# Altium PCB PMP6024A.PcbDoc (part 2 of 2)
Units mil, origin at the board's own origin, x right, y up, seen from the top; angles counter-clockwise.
Board outline 5700 x 1771.65 mil, 2 copper layers (Top Layer, Bottom Layer), stack 62 mil thick; 185 components, 92 nets, 398 pads, 91 vias.
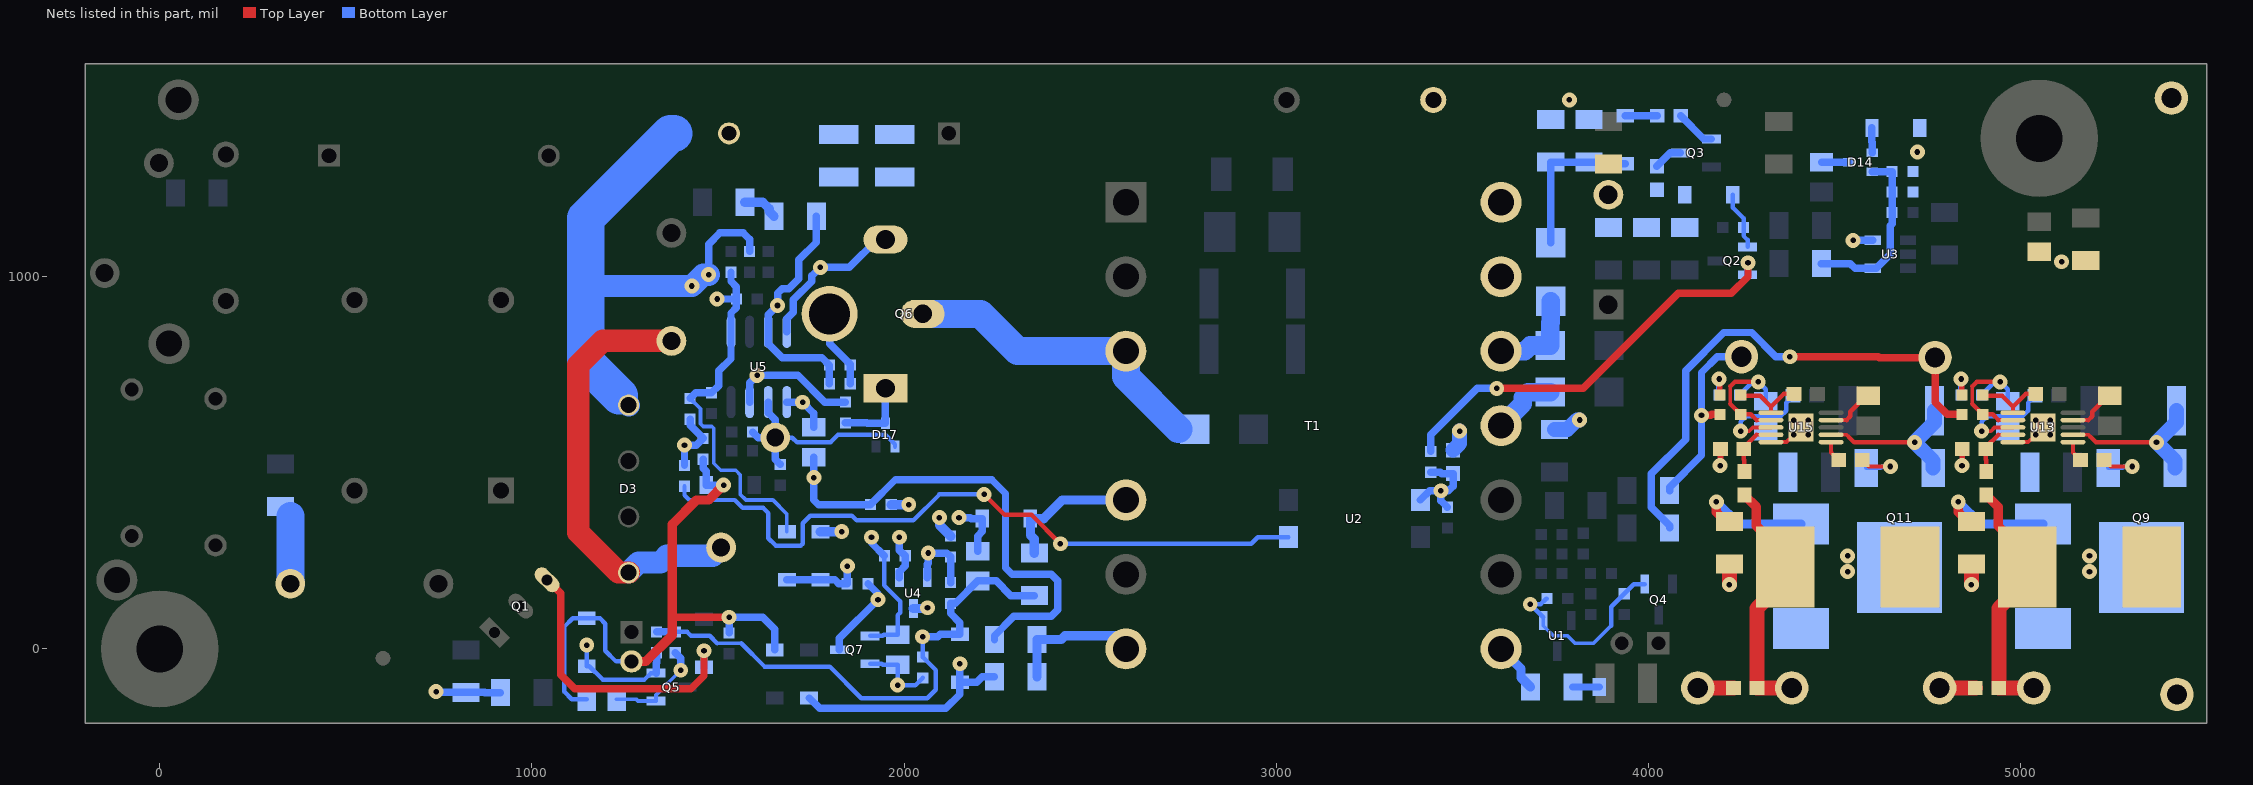
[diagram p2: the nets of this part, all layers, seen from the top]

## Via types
v1: diameter 40, hole 15, Top Layer to Bottom Layer, 82 vias
v2: diameter 25, hole 15, Top Layer to Bottom Layer, 8 vias
v3: diameter 40, hole 15, Top Layer to Bottom Layer, tented bottom, 1 vias

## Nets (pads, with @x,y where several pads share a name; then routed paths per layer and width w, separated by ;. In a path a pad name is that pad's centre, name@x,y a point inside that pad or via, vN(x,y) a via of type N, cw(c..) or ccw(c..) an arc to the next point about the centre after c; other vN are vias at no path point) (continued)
NetC24_1: C24.1 D11.1 R13.2 R17.2 R27.1 R35.2 R40.2 | length 1447.8
  Bottom Layer w10: 1497.5,15 1562.5,15
  Bottom Layer w12: R13.2@1385,45.5 1417,45.5 1427.5,35 1477.5,35 1497.5,15 ; 1562.5,15 1625,-47.5 1800,-47.5 1885,-132.5 2062.5,-132.5 2085,-110 2085,-57 R27.1@2050,-22 v1(2050,32.5)
  Bottom Layer w20: R17.2@1335,45.5 R13.2@1380.5,45.5 ; v1(2050,32.5) 2090,32.5 2096.97,39.47 D11.1@2150,39.47 2150,70 2125,95 R35.2@2125,122 2137,122 R40.2@2197.5,182.5 2247.5,182.5 2287.09,142.91 C24.1@2350,142.91
NetC25_2: C25.2 R19.1 R44.1 | length 1319.5
  Bottom Layer w20: R44.1@1757.5,515 v1(1757.5,460) 1757.5,400 1770,387.5 C25.2@1909.5,387.5 1977,455 2235,455 2272.5,417.5 2272.5,217.5 2290,200 2395,200 2412.5,182.5 2412.5,105 2395,87.5 2295,87.5 2242.91,35.41 R19.1@2242.91,25
NetC26_1: C26.1 R24.1 R45.2 U5.3 | length 644.7
  Bottom Layer w20: R24.1@1764.59,1162.5 1764.59,1092.09 1717.5,1045 1717.5,995 1690,967.5 1672.5,967.5 1660,955 v1(1660,922.5) 1635,897.5 U5.3@1635,851.99 1635,820 1672.5,782.5 1779.5,782.5 R45.2@1799.5,762.5 C26.1@1799.5,712.5
NetC27_1: C27.1 D20.2 D21.1 R7.2 | length 418.7
  Bottom Layer w20: D21.1@3737.5,1091.24 C27.1@3737.5,1307.91 R7.2@3840,1307.91 3892.09,1307.91 3896.97,1303.03 D20.2@3937.5,1303.03
NetC35_1: C35.1 D14.2 R21.2 R29.1 R41.2 U3.4 | length 483.7
  Bottom Layer w20: R21.2@4464.59,1035 4542.5,1035 4554.9,1022.6 U3.4@4602.76,1022.6 4612.6,1022.6 4650,1060 4650,1137.5 4654.5,1142 R29.1@4654.5,1172.5 C35.1@4654.5,1227.5 4654.5,1254.5 R41.2@4654.5,1282.5 4628.68,1282.5 4628.09,1281.91 D14.2@4601.5,1281.91
NetC66_1: C66.1 U13.9 | length 133.7
  Top Layer w10: U13.9@5140.71,614.69 5182.19,614.69
  Top Layer w12: 5182.19,614.69 5192.5,625 5192.5,637.5 5235,680 C66.1@5240,680
NetC68_1: C68.1 R46.1 R77.1 U13.2 | length 379.2
  Top Layer w10: 4870,658 4870,705 ; 4940.31,614.69 U13.2@4979.29,614.69
  Top Layer w12: 4870,658 R77.1@4898,630 4925,630 4940.31,614.69 ; 4870,705 4882.5,717.5 v1(4945,717.5)
  Bottom Layer w12: R46.1@4895.5,682.5 4930.5,717.5 v1(4945,717.5) 4965,697.5 C68.1@4965,665
NetC70_1: C70.1 R82.2 U13.4 | length 152.2
  Top Layer w10: 4940.31,575.32 U13.4@4979.29,575.32
  Top Layer w12: R82.2@4907.5,476.5 4907.5,507.5 4906.5,508.5 C70.1@4906.5,537.5 4906.5,541.5 4940.31,575.32
NetC76_1: C76.1 U15.9 | length 133.7
  Top Layer w10: U15.9@4490.71,614.69 4532.19,614.69
  Top Layer w12: 4532.19,614.69 4542.5,625 4542.5,637.5 4585,680 C76.1@4590,680
NetC78_1: C78.1 R48.1 R87.1 U15.2 | length 379.2
  Top Layer w10: 4220,658 4220,705 ; 4290.31,614.69 U15.2@4329.29,614.69
  Top Layer w12: 4220,658 R87.1@4248,630 4275,630 4290.31,614.69 ; 4220,705 4232.5,717.5 v1(4295,717.5)
  Bottom Layer w12: R48.1@4245.5,682.5 4280.5,717.5 v1(4295,717.5) 4315,697.5 C78.1@4315,665
NetC80_1: C80.1 R92.2 U15.4 | length 152.2
  Top Layer w10: 4290.31,575.32 U15.4@4329.29,575.32
  Top Layer w12: R92.2@4257.5,476.5 4257.5,507.5 4256.5,508.5 C80.1@4256.5,537.5 4256.5,541.5 4290.31,575.32
NetC81_1: C81.1 Q5.1 R13.1 | length 271.3
  Bottom Layer w10: C81.1@1227.5,-135 1280,-135 1284.9,-139.9 Q5.1@1333.66,-139.9 1333.66,-123.84 v1(1400,-57.5)
  Bottom Layer w20: R13.1@1385,-10.5 1400,-25.5 v1(1400,-57.5)
NetD1_2: D1.2 D21.2 T1.12 | length 257.8
  Bottom Layer w50: T1.12@3603.94,800 3667.5,800 3682.5,815 D1.2@3736.26,815 3736.26,876.26 3737.5,877.5 D21.2@3737.5,933.76
NetD3_1: D3.1 L1.1 RV1.2 | length 1182.5
  Top Layer w60: D3.1@1260,205 1232.5,205 1125,312.5 1125,762.5 1190,827.5 L1.1@1375,827.5
  Bottom Layer w60: D3.1@1260,205 1287,232 1344.5,232 1362.5,250 1485.8,250 RV1.2@1508.17,272.36
NetD4_2: D4.2 Q6.2 T1.3 | length 856.1
  Bottom Layer w75: Q6.2@2050,900 2205,900 2305,800 T1.3@2596.06,800 2596.06,731.44 2737.5,590
NetD5_2: D5.2 T1.11 | length 179.2
  Bottom Layer w50: T1.11@3603.94,600 3662.5,658.56 3662.5,675 3677.5,690 D5.2@3736.26,690
NetD6_1: D6.1 Q2.1 R5.1 | length 156.4
  Bottom Layer w12: D6.1@4226.97,1220 4226.97,1185.53 4255.5,1157 R5.1@4255.5,1132.5 4255.5,1109.5 4266.34,1098.66 Q2.1@4266.34,1079.9
NetD7_2: D7.2 R8.2 | length 70.9
  Bottom Layer w20: R8.2@3797.09,-102.5 D7.2@3868.03,-102.5
NetD9_2: D9.2 Q1.3 | length 797.9
  Top Layer w20: Q1.3@1040.71,185.71 1077.5,148.92 1077.5,-70 1115,-107.5 1427.5,-107.5 1462.5,-72.5 v3(1462.5,-5)
  Bottom Layer w20: D9.2@1462.5,-49.47 v3(1462.5,-5)
NetD10_2: D10.2 D11.2 R12.2 | length 613.6
  Bottom Layer w20: D10.2@1745,-131.97 1773.03,-160 2112.5,-160 2150,-122.5 D11.2@2150,-89.47 ; v1(2150,-40) D11.2@2150,-89.47 ; R12.2@2242.91,-75 2210,-75 2195.53,-89.47 D11.2@2150,-89.47
NetD12_1: D12.1 Q5.2 R17.1 | length 320.2
  Bottom Layer w12: v1(1147.5,10) D12.1@1147.5,-46.97 1154.47,-46.97 1190,-82.5 1302.5,-82.5 1319.9,-65.1 Q5.2@1333.66,-65.1
  Bottom Layer w20: Q5.2@1333.66,-65.1 1333.66,-38.84 1335,-37.5 R17.1@1335,-10.5
NetD14_1: D14.1 D15.2 | length 67.3
  Bottom Layer w20: D15.2@4600.53,1400 4600.53,1361.97 4601.5,1361 D14.1@4601.5,1333.09
NetD14_3: D14.3 R22.1 | length 73.5
  Bottom Layer w20: R22.1@4465,1307.5 D14.3@4538.5,1307.5
NetD16_1: D16.1 D19.2 R36.2 | length 214.1
  Bottom Layer w20: D19.2@1685,185.53 D16.1@1775,185.53 1814.47,185.53 1825,175 R36.2@1847,175 1847,222 v1(1847.5,222.5)
NetD17_3: D17.3 Q6.1 R30.2 | length 201.2
  Bottom Layer w20: R30.2@1842.5,607 1900,607 1900.5,606.5 D17.3@1950,606.5 Q6.1@1950,700
NetD18_1: D18.1 R40.1 | length 157
  Bottom Layer w20: v1(2147.5,352.5) 2177.5,352.5 2180,350 D18.1@2210.53,350 2210.53,315.53 2197.5,302.5 R40.1@2197.5,262.5
NetD19_1: D19.1 R25.2 R31.2 R32.2 R34.2 U5.1 | length 1019.1
  Bottom Layer w10: R31.2@1425,673 1453,645 1453,605.03 1460.53,597.5 1483.5,597.5 1488.5,592.5 1488.5,499 1507.5,480 1547.5,480 1560,467.5 1560,415 1575,400 1647.5,400 1685,362.5 D19.1@1685,314.47
  Bottom Layer w20: R31.2@1425,673 1440,688 R25.2@1482.5,688 1502,707.5 1502,747 1535,780 U5.1@1535,851.99 1535,902.5 1549.5,917 R34.2@1549.5,940 ; v1(1497.5,940) R34.2@1549.5,940 ; R32.2@1535,1012 1535,987.5 1549.5,973 R34.2@1549.5,940
NetD20_1: D20.1 R6.1 | length 86.2
  Bottom Layer w20: D20.1@3937.5,1431.97 3981.97,1431.97 3982.5,1432.5 R6.1@4023.5,1432.5
NetD30_1: D30.1 L6.1 Q9.4
  other v1: 5185,207.5 5185,250
NetD30_2: D30.2 L8.2 | length 325.2
  Top Layer w25: v1(4832.5,395) 4832.5,367.5 4857.91,342.09 L8.2@4867.5,342.09
  Bottom Layer w25: v1(4832.5,395) 4892.01,335.49 D30.2@5060,335.49
NetD32_1: D32.1 L7.1 Q11.4
  other v1: 4535,207.5 4535,250
NetD32_2: D32.2 L9.2 | length 325.2
  Top Layer w25: v1(4182.5,395) 4182.5,367.5 4207.91,342.09 L9.2@4217.5,342.09
  Bottom Layer w25: v1(4182.5,395) 4242.01,335.49 D32.2@4410,335.49
NetF1_2: F1.2 L3.2 | length 181.9
  Bottom Layer w75: F1.2@350.98,175 350.98,356.93
NetQ2_2: Q2.2 R18.2 | length 1143.4
  Top Layer w20: v1(3592.5,700) 3825,700 4080,955 4222.5,955 4267.5,1000 v1(4267.5,1037.5)
  Bottom Layer w20: R18.2@3415,530.5 3415,575 3540,700 v1(3592.5,700) ; Q2.2@4266.34,1005.1 4266.34,1036.34 v1(4267.5,1037.5)
NetQ3_1: Q3.1 R6.2 | length 108.3
  Bottom Layer w20: R6.2@4086.5,1432.5 4149.09,1369.9 Q3.1@4168.84,1369.9
NetQ3_3: Q3.3 R9.2 | length 78.6
  Bottom Layer w20: R9.2@4022.5,1296.5 4058.5,1332.5 Q3.3@4086.16,1332.5
NetQ4_1: Q4.1 R10.1 R14.2 U1.1 | length 510.4
  Bottom Layer w10: U1.1@3717.6,84.9 U1.1@3717.6,76.34 3717.6,62.4 3745,35 3782.5,35 3802.5,15 3852.5,15 3900,62.5
  Bottom Layer w12: U1.1@3717.6,84.9 v1(3682.5,120) 3710,120 3725,135 R14.2@3727,135 ; 3900,62.5 3900,113 R10.1@3935,148 3960.84,173.84 Q4.1@3990.1,173.84
NetQ6_3: Q6.3 R38.2 R39.2 U5.4 | length 416.4
  Bottom Layer w20: U5.4@1685,851.99 1685,887.5 1702.5,905 1702.5,937.5 1752.5,987.5 1752.5,1002.5 v1(1775,1025) 1852.5,1025 1927.5,1100 Q6.3@1950,1100
NetQ7_1: Q7.1 R28.1 R33.2 | length 372.4
  Bottom Layer w12: Q7.1@1908.84,34.9 1942.4,34.9 1945,37.5 R28.1@1982.5,37.5 1982.5,90 1990,97.5 1990,127.5 1947,170.5 R33.2@1947,250
  Bottom Layer w20: v1(1912.5,300) 1912.5,284.5 R33.2@1947,250
NetQ7_2: Q7.2 R27.2 R28.2 | length 205.3
  Bottom Layer w12: Q7.2@1908.84,-39.9 1939.9,-39.9 1942.5,-42.5 R28.2@1982.5,-42.5 v1(1982.5,-97.5) 2030.5,-97.5 R27.2@2050,-78
NetQ7_3: Q7.3 R36.1 | length 231.7
  Bottom Layer w20: Q7.3@1826.16,-2.5 1826.16,28.66 v1(1930,132.5) 1930,148 R36.1@1903,175
NetQ9_1: Q9.1 R150.2 | length 149.5
  Top Layer w12: R150.2@5224,507.5 5241.5,490 v1(5300,490)
  Bottom Layer w12: Q9.1@5235.24,486.36 5273.86,486.36 5277.5,490 v1(5300,490)
NetQ9_3: Q9.3 R79.1 U13.7 | length 429.2
  Top Layer w10: U13.7@5140.71,575.32 5182.19,575.32 5187.5,570
  Top Layer w12: 5187.5,570 5202.5,555 v1(5365,555)
  Bottom Layer w40: Q9.3@5414.76,486.36 5414.76,505.24 v1(5365,555) 5418.64,608.64 R79.1@5418.64,640
NetQ11_1: Q11.1 R151.2 | length 149.5
  Top Layer w12: R151.2@4574,507.5 4591.5,490 v1(4650,490)
  Bottom Layer w12: Q11.1@4585.24,486.36 4623.86,486.36 4627.5,490 v1(4650,490)
NetQ11_3: Q11.3 R89.1 U15.7 | length 429.2
  Top Layer w10: U15.7@4490.71,575.32 4532.19,575.32 4537.5,570
  Top Layer w12: 4537.5,570 4552.5,555 v1(4715,555)
  Bottom Layer w40: Q11.3@4764.76,486.36 4764.76,505.24 v1(4715,555) 4768.64,608.64 R89.1@4768.64,640
NetR1_2: R1.2 R4.1 | length 173.9
  Bottom Layer w20: v1(742.5,-115) 744.59,-117.09 R4.1@822.5,-117.09 872.91,-117.09 873.33,-117.5 R1.2@915.41,-117.5
NetR8_1: R8.1 T1.8 | length 135.2
  Bottom Layer w25: T1.8@3603.94,0 3657.5,-53.56 3657.5,-77.09 R8.1@3682.91,-102.5
NetR12_1: R12.1 R19.2 T1.7 | length 322.1
  Bottom Layer w25: R12.1@2357.09,-75 R19.2@2357.09,25 2422.5,25 2432.5,35 T1.7@2575,35
NetR18_1: R18.1 R23.2 R50.2 U2.1 | length 250.1
  Bottom Layer w20: U2.1@3387.17,400 3412.17,425 v1(3442.5,425) ; R18.1@3415,474.5 3440.5,474.5 3444,471 R50.2@3475,471 3475,437.5 3462.5,425 v1(3442.5,425) ; R23.2@3460,380.5 3442.5,398 v1(3442.5,425)
NetR20_1: R20.1 R24.2 | length 98
  Bottom Layer w25: R20.1@1572.09,1200 1620,1200 1637.5,1182.5 1637.5,1175.41 R24.2@1650.41,1162.5
NetR30_1: R30.1 U5.7 | length 347.6
  Bottom Layer w20: U5.7@1585,663.01 1585,715 v1(1605,735) 1715,735 1787,663 R30.1@1842.5,663
NetR31_1: R31.1 R37.2 R43.1 | length 178
  Bottom Layer w20: R43.1@1410,493 v1(1410,547.5) 1442,547.5 R37.2@1460,565.5 1425,600.5 R31.1@1425,617
NetR33_1: R33.1 U4.1 | length 121.5
  Bottom Layer w20: v1(1987.5,300) 1987.5,265.5 R33.1@2003,250 2003,223 1987.6,207.6 U4.1@1987.6,191.34
NetR35_1: R35.1 R42.2 U4.2 | length 200.6
  Bottom Layer w20: U4.2@2062.4,191.34 2062.4,227.4 2065,230 v1(2065,257.5) 2114.5,257.5 R42.2@2125,247 R35.1@2125,178
NetR43_2: R43.2 U2.3 | length 1904.5
  Top Layer w12: v1(2215,415) 2270,360 2342.5,360 v1(2420,282.5)
  Bottom Layer w12: R43.2@1410,437 1410,412.5 1422.5,400 1545,400 1566.25,378.75 1621.25,378.75 1635,365 1635,297.5 1655,277.5 1722.5,277.5 1727.5,282.5 1727.5,337.5 1747.5,357.5 1860,357.5 1872.5,345 2025,345 2095,415 v1(2215,415) ; v1(2420,282.5) 2932.5,282.5 2950,300 U2.3@3032.83,300
NetR44_2: R44.2 U5.5 | length 122.6
  Bottom Layer w20: U5.5@1685,663.01 1726.99,663.01 v1(1727.5,662.5) 1757.5,632.5 R44.2@1757.5,595
NetR47_2: R47.2 U13.3 | length 298.5
  Top Layer w10: v1(4895,585) 4920,585 4930,595 U13.3@4979.29,595
  Bottom Layer w12: v1(4895,585) 4895,610 4910,625 5005,625 5020,640 5020,661.5 R47.2@5038.5,680
NetR49_2: R49.2 U15.3 | length 293.5
  Top Layer w10: v1(4247.5,585) 4270,585 4280,595 U15.3@4329.29,595
  Bottom Layer w12: v1(4247.5,585) 4247.5,610 4262.5,625 4355,625 4370,640 4370,661.5 R49.2@4388.5,680
NetR75_2: R75.2 R81.2 U13.1 | length 177.2
  Top Layer w10: U13.1@4979.29,634.37 4979.29,650.71
  Top Layer w12: R81.2@4906.5,680 4950,680 4979.29,650.71 5013.58,685 R75.2@5041,685
NetR85_2: R85.2 R91.2 U15.1 | length 177.2
  Top Layer w10: U15.1@4329.29,634.37 4329.29,650.71
  Top Layer w12: R91.2@4256.5,680 4300,680 4329.29,650.71 4363.58,685 R85.2@4391,685
NetR150_1: R150.1 U13.6 | length 56.5
  Top Layer w10: 5140.71,527.8 U13.6@5140.71,555.63
  Top Layer w12: 5140.71,527.8 R150.1@5161,507.5
NetR151_1: R151.1 U15.6 | length 56.5
  Top Layer w10: 4490.71,527.8 U15.6@4490.71,555.63
  Top Layer w12: 4490.71,527.8 R151.1@4511,507.5
PGND: C2.2 C10.2 C17.2 C20.2 C22.2 C24.2 C25.1 C26.2 C36.2 C81.2 D3.4 D8.2 D12.2 D13.2 D16.2 D17.1 D18.2 HTSK1.1 R37.1 R38.1 R39.1 R42.1 R45.1 RV1.1 T1.5 U4.3 U5.6 | length 4503.9
  Top Layer w20: 1377.5,85 v1(1530,85)
  Top Layer w25: C17.2@1267.5,-33.74 1306.26,-33.74 1377.5,37.5 1377.5,85 1377.5,335 1442.5,400 1475,400 v1(1515,440)
  Bottom Layer w12: C81.2@1147.5,-135 1107.5,-135 1087.5,-115 1087.5,60 1109.47,81.97 D12.2@1147.5,81.97 1183.03,81.97 1197.5,67.5 1197.5,-5 1226.24,-33.74 C17.2@1267.5,-33.74 ; RV1.1@1653.83,567.64 1699.86,567.64 1712.5,555 1802.5,555 1822.5,575 1950,575 1975.59,549.41 D17.1@1975.59,543.5
  Bottom Layer w20: R37.1@1460,509.5 1460,485 1468.03,476.97 D13.2@1468.03,440 v1(1515,440) ; v1(1475,1005.5) 1475,1087.5 1505,1117.5 1567.5,1117.5 1585,1100 C36.2@1585,1068 ; C10.2@1530,43 v1(1530,85) 1620,85 1652.5,52.5 D8.2@1652.5,-3.03 ; C20.2@1593,582.5 1607.86,567.64 RV1.1@1653.83,567.64 ; U5.6@1635,663.01 1635,635 1653.83,616.17 RV1.1@1653.83,567.64 ; C22.2@1667.5,495.5 1653.83,509.17 RV1.1@1653.83,567.64 ; HTSK1.1@1800,900 1800,820 1855.5,764.5 R45.1@1855.5,762.5 C26.2@1855.5,712.5
  Bottom Layer w25: D16.2@1775,314.47 1831.97,314.47 v1(1832.5,315) ; C25.1@1965.5,387.5 v1(2012.5,387.5) ; U4.3@2025,108.66 2061.16,108.66 v1@2062.5,110 ; v1(2095,352.5) 2095,333 R42.1@2125,303 ; C24.2@2350,257.09 2350,295 2339.47,305.53 D18.2@2339.47,350 2375,350 2425,400 T1.5@2596.06,400
  Bottom Layer w60: 1145,975 v1(1430,975) 1460.5,1005.5 v1(1475,1005.5) ; 1235,680 D3.4@1260,655
  Bottom Layer w100: 1235,680 1145,770 1145,975 1145,1157.5 1372.5,1385 1382.09,1385
  other v1: 2063.03,110.53
PWM1_IADJ: J4.1 R52.2 R77.2 | length 1427.2
  Top Layer w20: v1(4380,785) 4617.5,785 4620,782.5 J4.1@4770,782.5 4770,662.5 4802.5,630 R77.2@4842,630
  Bottom Layer w20: R52.2@4057.09,325 4057.09,330.41 4007.5,380 4007.5,470 4100,562.5 4100,747.5 4202.5,850 4277.5,850 4342.5,785 v1(4380,785)
PWM2_IADJ: J5.1 R53.2 R87.2 | length 528.5
  Top Layer w20: v1(4142.5,627.5) 4167.5,627.5 4170,630 R87.2@4192,630
  Bottom Layer w20: R53.2@4057.09,425 4057.09,434.59 4142.5,520 v1(4142.5,627.5) 4142.5,742.5 4185,785 J5.1@4250,785
SGND: C1.1 C5.2 C6.2 C7.2 C9.2 C27.2 C35.2 C40.1 C42.2 C64.1 C68.2 C70.2 C72.2 C74.1 C78.2 C80.2 C82.2 D6.2 D15.1 J6.1 J7.1 J8.1 J11.1 L8.1 L9.1 R7.1 R9.1 R41.1 R46.2 R48.2 R50.1 R51.2 R76.2 R81.1 R91.1 T1.13 T1.14 U3.5 U13.5 U13.11 U15.5 U15.11 | length 893.2
  Top Layer w10: U15.5@4329.29,555.63 4370.63,555.63 v2(4390.31,575.31) ; U13.5@4979.29,555.63 5020.63,555.63 v2(5040.31,575.31)
  Top Layer w15: v1(4190,725) 4192,723 R91.1@4192,682.5 ; v1(4192.5,492.5) 4193.5,493.5 C80.2@4193.5,537.5 ; v1(4840,725) 4842,723 R81.1@4842,682.5 ; v1(4842.5,492.5) 4843.5,493.5 C70.2@4843.5,537.5
  Top Layer w40: J11.1@4132.5,-105 C82.2@4228.5,-105 ; v1(4217.5,172.5) L9.1@4217.5,227.91 ; J6.1@4782.5,-105 C72.2@4878.5,-105 ; v1(4867.5,172.5) L8.1@4867.5,227.91
  Bottom Layer w15: R48.2@4189.5,682.5 4189.5,724.5 v1(4190,725) ; R46.2@4839.5,682.5 4839.5,724.5 v1(4840,725)
  Bottom Layer w20: v1(4550,1097.5) 4550.1,1097.4 U3.5@4602.76,1097.4
  Bottom Layer w40: R50.1@3475,534 3492.5,551.5 v1(3492.5,585) ; R51.2@3747.5,589.59 3782.09,589.59 3807.5,615 v1(3815,615)
  other v1: 5110,1040 4722.5,1335 3787.5,1475
  other v2: 4429.69,575.31 5079.69,575.31 4390.31,614.68 4429.69,614.68 5040.31,614.68 5079.69,614.68
VLED1: C72.1 J9.1 L6.2 R82.1 | length 689.4
  Top Layer w25: R82.1@4907.5,413.5 4940,381 4940,330 5017.98,252.02 L6.2@5017.98,220
  Top Layer w40: L6.2@5017.98,220 5017.98,185.48 4941.5,109 C72.1@4941.5,-105 J9.1@5035,-105
VLED2: C82.1 J13.1 L7.2 R92.1 | length 689.4
  Top Layer w25: R92.1@4257.5,413.5 4290,381 4290,330 4367.98,252.02 L7.2@4367.98,220
  Top Layer w40: L7.2@4367.98,220 4367.98,185.48 4291.5,109 C82.1@4291.5,-105 J13.1@4385,-105
pads on no net: FID1.1 FID2.1 FID3.1 FID4.1 T1.2 T1.4 T1.6 T1.10 U3.1 U3.2

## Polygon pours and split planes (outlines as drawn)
EGND on Bottom Layer "Bottom Layer-EGND" (solid, remove dead copper, pour order 15): 157.5,307.5 17.5,307.5 -57.5,382.5 -105,382.5 -157.5,330 -157.5,-30 -32.5,-155 57.5,-155 155,-57.5 155,195 177.5,217.5 177.5,287.5
NetQ6_3 on Bottom Layer "Bottom Layer-NetQ6_3" (solid, remove dead copper, pour order 20): 1772.5,1300 2035,1300 2035,1087.5 2007.5,1060 2005,1062.5 1902.5,1062.5 1875,1090 1875,1217.5 1850,1242.5 1772.5,1242.5
NetD30_1 on Bottom Layer "Bottom Layer-NetD30_1" (solid, remove dead copper, pour order 23): 4985,0 5345,0 5440,95 5440,340 5212.5,340 5167.5,295 5167.5,140 5137.5,110 4985,110
SGND on Bottom Layer "Bottom Layer-SGND" (solid, remove dead copper, pour order 28): 5035,630 5012.5,607.5 4935,607.5 4935,575 4920,560 4892.5,560 4877.5,575 4865,587.5 4865,677.5 4865,735 4852.5,747.5 4827.5,747.5 4812.5,732.5 4812.5,465 4830,447.5 4857.5,420 5050,420 5050,522.5 5095,567.5 5095,617.5 5082.5,630
NetD32_1 on Bottom Layer "Bottom Layer-NetD32_1" (solid, remove dead copper, pour order 21): 4335,0 4695,0 4790,95 4790,340 4562.5,340 4517.5,295 4517.5,140 4487.5,110 4335,110
SGND on Bottom Layer "Bottom Layer-SGND" (solid, remove dead copper, pour order 27): 4385,630 4362.5,607.5 4285,607.5 4285,575 4270,560 4242.5,560 4227.5,575 4215,587.5 4215,677.5 4215,735 4202.5,747.5 4177.5,747.5 4162.5,732.5 4162.5,465 4180,447.5 4207.5,420 4400,420 4400,522.5 4445,567.5 4445,617.5 4432.5,630
+50V on Bottom Layer "Bottom Layer-50V" (solid, remove dead copper, pour order 17): 4462.5,422.5 4462.5,630 4432.5,660 4432.5,747.5 4537.5,747.5 4675,610 4675,592.5 4652.5,570 4547.5,570 4517.5,540 4517.5,422.5
+50V on Bottom Layer "Bottom Layer-50V" (solid, remove dead copper, pour order 18): 5112.5,422.5 5112.5,630 5082.5,660 5082.5,745 5190,745 5325,610 5325,592.5 5302.5,570 5197.5,570 5167.5,540 5167.5,422.5
+50V on Bottom Layer "Bottom Layer-50V" (solid, remove dead copper, pour order 16): 3855,652.5 3855,1045 3865,1055 4210,1055 4210,987.5 4232.5,965 4300,965 4322.5,987.5 4322.5,1282.5 4410,1282.5 4410,985 4395,970 4395,932.5 4427.5,900 4477.5,900 4510,932.5 5072.5,932.5 5192.5,812.5 5192.5,702.5 5085,702.5 5085,747.5 4980,852.5 4737.5,852.5 4675,790 4675,610 4640,575 4512.5,575 4432.5,655 4432.5,800 4402.5,830 4352.5,830 4297.5,885 4190,885 4052.5,747.5 3980,747.5 3935,702.5 3935,652.5
PGND on Top Layer "Top Layer-PGND" (solid, remove dead copper, pour order 26): 1225,75 1325,75 1375,125 1375,575 1355,595 1355,625 1355,700 1450,700 1525,775 1525,900 1475,950 1400,950 1400,1000 1425,1000 1450,1025 1500,1025 1550,1075 1775,1075 1875,975 1875,800 1925,750 2000,750 2225,525 2600,525 2655,470 2655,-70 2575,-150 1225,-150
NetD30_1 on Top Layer "Top Layer-NetD30_1" (solid, remove dead copper, pour order 25): 5432.5,330 5232.5,330 5167.5,265 5167.5,177.5 5232.5,112.5 5432.5,112.5
NetD32_1 on Top Layer "Top Layer-NetD32_1" (solid, remove dead copper, pour order 24): 4782.5,330 4582.5,330 4517.5,265 4517.5,177.5 4582.5,112.5 4782.5,112.5
DGND on Top Layer "Top Layer-DGND" (solid, remove dead copper, pour order 22): 3525,225 3600,300 3650,300 3710,360 3710,500 3930,500 3970,460 3970,305 4075,200 4075,-25 4025,-75 4025,-150 3575,-150 3525,-100
SGND on Top Layer "Top Layer-SGND" (solid, remove dead copper, pour order 19): 3350,1525 3350,1432.5 3425,1357.5 3425,597.5 3397.5,570 3397.5,467.5 3365,435 3365,275 3475,275 3525,325 3525,425 3590,490 3660,490 3700,530 3970,530 4000,500 4000,325 4125,200 4125,-25 4075,-75 4075,-150 5425,-150 5450,-125 5450,1475 5400,1525

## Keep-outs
Keep-Out Layer:
  text ".Layer_Name" at 377,-1058.49 h60

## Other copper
Top Layer:
  rectangle net +50V: 4312.5,1222.5 4385,1327.5
  rectangle net SGND: 5020,1017.5 5210,1092.5
  pour cut-out: 1377.5,327.5 1450,400 1625,400 1625,125 1377.5,125
  text ".Layer_Name" at 377,-1058.49 h60
Bottom Layer:
  rectangle net NetC14_2: -42.5,1192.5 65,1345
  rectangle net NetF1_2: 295,337.5 387.5,407.5
  rectangle net NetC11_1: 260,470 362.5,535
  rectangle net NetC12_2: 137.5,1192.5 220,1360
  rectangle net PGND: 1355,1360 2035,1525
  rectangle net SGND: 3702.5,1397.5 3875,1495
  rectangle net SGND: 3855,1107.5 4135,1260
  rectangle net SGND: 4695,1212.5 4747.5,1425
  text ".Layer_Name" at 377,-1058.49 h60

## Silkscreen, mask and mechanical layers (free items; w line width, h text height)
Top Overlay:
  text "N" at 122.5,1432.5 h50
  text "L" at 90,765 h40
  text "TI" at 2240,457.5 h40 r90
  text ".CopyrightYear" at 2240,181.5 h40 r90
  text "G" at 7.5,162.5 h40
  text "MADE IN U.S." at 2305,117.5 h40 r90
  text "©" at 2243.52,115 h75 r90
  text "SGND" at 4105,-47.5 h30
  text "VLED2" at 4437.5,-92.5 h30
  text "SGND" at 4617.5,-92.5 h30
  text "VLED1" at 5090,-92.5 h30
  text "FLY BUCK BOARD" at 1567.5,-140 h50
  text ".Layer_Name" at 377,-1058.49 h60
Bottom Overlay:
  lines w7: 1065,-15 1085,-35 1085,-110 1097.5,-122.5
  text ".PRJ_Number" at 704,1485 h40
  text "PCB P/N:" at 1042.5,1485 h40
  text ".PCB_Rev" at 872.5,1415 h40
  text "REV:" at 1040,1415 h40
  text ".Layer_Name" at 377,-1058.49 h60
Top Paste:
  text ".Layer_Name" at 377,-1058.49 h60
Bottom Paste:
  text ".Layer_Name" at 377,-1058.49 h60
Top Solder:
  text ".Layer_Name" at 377,-1058.49 h60
  text ".Layer_Name" at 377,-1058.49 h60
Bottom Solder:
  rectangle: 4310,916 4378,990
  rectangle: 4345,263 4411,337
  text ".Layer_Name" at 377,-1058.49 h60
Drill Guide:
  text ".Layer_Name" at 377,-1058.49 h60
M1 Board Outline:
  the board outline again, w10
  text ".Layer_Name" at 377,-1058.49 h60
M2 Board Dimensions:
  text ".Layer_Name" at 377,-1058.49 h60
M3 3D STEP Top:
  text ".Layer_Name" at 377,-1058.49 h60
M4 3D STEP Bottom:
  text ".Layer_Name" at 377,-1058.49 h60
M5 Assembly Top:
  lines w10: -492,-1130.17 6108,-1130.17 ; -492,-926.83 6110,-926.83 ; -492,-723.5 -492,-1333.5 3513,-1333.5 6110,-1333.5 6110,-723.5 -491.5,-723.5 -491.5,-1333.5 1084,-1333.5 ; 1973,-1333.5 1973,-723.5 ; 3240,-926.83 3240,-723.5 ; 4080,-926.83 4080,-723.5 ; 4702,-1340 4702,-1137.17
  text "COMPONENTS MARKED 'DNP' SHOULD NOT BE POPULATED, AND MAY NOT BE IN BILL OF MATERIALS" at 953.5,-518.5 h60
  text "ASSEMBLY VARIANT:" at 953,-634 h60
  text ".VariantName" at 1989,-634 h60
  text "PCB VIEWED FROM TOP SIDE" at -428.5,-855.67 h60
  text "BOARD #:" at 2048,-855.67 h60
  text ".PRJ_Number" at 2593.5,-855.67 h60
  text "REV:" at 3438,-855.67 h60
  text ".PCB_Rev" at 3729.5,-855.67 h60
  text "SVN REV:" at 4276,-855.67 h60
  text ".VersionControl_RevNumber" at 4782,-855.67 h60
  text "IGNORE ->" at -428.5,-1058.49 h60
  text "PLOT NAME =" at -428.5,-1264.34 h60
  text ".plot_File_Name" at 377,-1264.34 h60
  text "GENERATED    :" at 2050,-1264.34 h60
  text ".Print_Date" at 2919.5,-1264.34 h60
  text ".Print_Time" at 3648.5,-1264.34 h60
  text "TEXAS INSTRUMENTS" at 4913,-1264.34 h60
M6 Assembly Bottom:
  lines w10: -492.5,-927.33 6109.5,-927.33 ; -490.5,-1130.67 6109.5,-1130.67 ; 915.5,-1340.5 915.5,-1137.67 ; 1537.5,-927.33 1537.5,-724 ; 2377.5,-927.33 2377.5,-724 ; 3644.5,-1334 3644.5,-724 ; 4533.5,-1334 6109,-1334 6109,-724 -492.5,-724 -492.5,-1334 2104.5,-1334 6109.5,-1334 6109.5,-724
  text "COMPONENTS MARKED 'DNP' SHOULD NOT BE POPULATED, AND MAY NOT BE IN BILL OF MATERIALS" at 5902,-518 h60
  text ".VariantName" at 4858,-634 h60
  text "ASSEMBLY VARIANT:" at 5897,-634 h60
  text ".VersionControl_RevNumber" at 835.5,-856.17 h60
  text "SVN REV:" at 1341.5,-856.17 h60
  text ".PCB_Rev" at 1888,-856.17 h60
  text "REV:" at 2179.5,-856.17 h60
  text ".PRJ_Number" at 3024,-856.17 h60
  text "BOARD #:" at 3569.5,-856.17 h60
  text "PCB VIEWED FROM BOTTOM SIDE" at 6046,-856.17 h60
  text "IGNORE ->" at 2347.85,-1058.49 h60
  text "TEXAS INSTRUMENTS" at 704.5,-1264.84 h60
  text ".Print_Time" at 1969,-1264.84 h60
  text ".Print_Date" at 2698,-1264.84 h60
  text "GENERATED    :" at 3567.5,-1264.84 h60
  text ".plot_File_Name" at 5240.5,-1264.84 h60
  text "PLOT NAME =" at 6046,-1264.84 h60
M9 Title Sheet:
  drawing of 57 lines, arcs and shapes, not listed
  text "1" at 539.84,7836.5 h70
  text "2" at 3035.5,7836.5 h70
  text "3" at 5524.84,7836.5 h70
  text "4" at 8031.51,7836.5 h70
  text "5" at 10530.5,7836.5 h70
  text "6" at 13035.5,7836.5 h70
  text "A" at -616.5,6693.5 h70
  text "A" at 14183.5,6693.5 h70
  text "B" at -616.5,4313.5 h70
  text "B" at 14183.5,4313.5 h70
  text "C" at -616.5,1938.5 h70
  text "C" at 14183.5,1938.5 h70
  text "PROJECT TITLE:" at 11143.5,77.5 h45
  text ".PRJ_Title" at 11193.5,-55.83 h70
  text "DESIGNED FOR:" at 11143.5,-223.5 h45
  text ".PRJ_Customer" at 11193.5,-363.5 h70
  text "D" at -616.5,-431.5 h70
  text "D" at 14183.5,-431.5 h70
  text "FILE NAME:" at 11143.5,-523.5 h45
  text ".PCB_File_Name_No_Path" at 11193.5,-643.5 h70
  text "Texas Instruments (TI) and/or its licensors do not warrant the accuracy or completeness of this specification" at 6174,-805.34 h45
  text "ENGINEER:" at 11143.5,-813.5 h45
  text "LAYOUT BY:" at 12648.5,-813.5 h45
  text "or any information contained therein. TI and/or its licensors do not warrant that this design will meet" at 6129.01,-918 h45
  text ".PRJ_Engineer" at 11193.5,-968.49 h70
  text ".PCB_Layout" at 12699,-968.49 h70
  text "the specifications, will be suitable for your application or fit for any particular purpose, or will operate in" at 6129.01,-1030.67 h45
  text ".Layer_Name" at 377,-1058.49 h60
  text "ALTIUM DESIGNER VERSION:" at 12648.5,-1123.5 h45
  text "an implementation. TI and/or its licensors do not warrant that the design is production worthy. You should" at 6129.01,-1143.33 h45
  text "completely validate and test your design implementation to confirm the system functionality for your application." at 6174,-1256 h45
  text ".print_Scale" at 11193.5,-1256.83 h70
  text ".Application_BuildNumber" at 12699,-1256.83 h70
  text "1" at 539.84,-1463.5 h70
  text "2" at 3035.5,-1463.5 h70
  text "3" at 5524.84,-1463.5 h70
  text "4" at 8031.51,-1463.5 h70
  text "5" at 10530.5,-1463.5 h70
  text "6" at 13035.5,-1463.5 h70
M10 Fab Notes:
  drawing of 203 lines, arcs and shapes, not listed
  text "DESIGN INFORMATION" at 12181.02,6610 h60
  text "(REFER ALSO ARRAY/PANEL PROFILING INFORMATION)" at 11819.46,6448.29 h60
  text "BOARD SIZE" at 11133.46,6444 h60
  text "5700MIL" at 11595.78,6316.18 h60
  text "X" at 12101.46,6316.18 h60
  text "1772MIL" at 12332.78,6316.18 h60
  text "Number of Layers :" at 11536.46,6119 h60
  text "2" at 12631.27,6109 h60
  text "MIN. TRACK WIDTH:" at 11536.46,5980 h60
  text "10" at 12632.7,5980 h60
  text "MIL" at 12787.46,5980 h60
  text "MIN. CLEARANCE:" at 11536.46,5848 h60
  text "7" at 12677.5,5847.5 h60
  text "MIL" at 12787.46,5848 h60
  text "MIN. VIA PAD SIZE:" at 11536.46,5716 h60
  text "40" at 12602.71,5716 h60
  text "MIL" at 12787.46,5716 h60
  text "0.05mm (2MIL)" at 12231.46,5574.29 h60
  text "MINIMUM ANNULAR RING" at 11207.23,5570 h60
  text "EXTERNAL" at 12939.46,5570 h60
  text "PER" at 11407.23,5452 h60
  text "IPC-D-275 CLASS 2 LEVEL C" at 11627.23,5452 h60
  text "MIL, HOLES" at 13115.46,5339.71 h60
  text "+/-" at 12723,5339 h60
  text "+/-" at 13577,5339 h60
  text "REGISTRATION TOLERANCES:" at 11207.23,5334 h60
  text "METAL" at 12407,5334 h60
  text "5" at 12983.2,5334 h60
  text "3" at 13816.2,5334 h60
  text "MIL" at 13932.46,5334 h60
  text "MATERIAL:" at 11132.46,5124.54 h60
  text "FR-4 High Tg" at 12118.9,4984.21 h60
  text "FR-4" at 11593.46,4975.64 h60
  text "OTHER" at 13041.46,4975.64 h60
  text "X" at 11397.5,4972.5 h60
  text "62 MIL (1.6mm) +/-10%" at 11873.56,4812.92 h60
  text "THICKNESS:" at 11207.23,4808.64 h60
  text "X" at 11745.4,4808.64 h60
  text "OTHER" at 13158.46,4808.64 h60
  text "TOLERANCE:" at 11207.23,4650.64 h60
  text "X" at 12046.53,4650.64 h60
  text "ANSI IPC-6012 TYPE 3 CLASS 2" at 12233.48,4650.64 h60
  text "OTHER +/-" at 12233.46,4494.64 h60
  text "BOW & TWIST:" at 11207.23,4337.64 h60
  text "X" at 12046.53,4337.64 h60
  text "ANSI IPC-6012 TYPE 3 CLASS 2" at 12233.48,4337.64 h60
  text "OTHER +/-" at 12233.46,4179.13 h60
  text "COPPER THICKNESS (FINISHED):" at 11132.46,4043.64 h60
  text "1.4MIL (1oz)" at 12012.46,3890.92 h60
  text "2MIL (1.4oz)" at 12779.46,3890.92 h60
  text "2.8MIL (2oz)" at 13506.46,3890.92 h60
  text "OUTER:" at 11489.46,3886.64 h60
  text "X" at 11884,3886 h60
  text "1.4MIL (1oz)" at 12362.46,3733.92 h60
  text "2.8MIL (2oz)" at 13206.46,3733.92 h60
  text "INNER SIGNAL:" at 11489.46,3729.64 h60
  text "DRILLING:" at 11132.46,3590.64 h60
  text "REFERENCE:" at 11207.23,3473.64 h60
  text "X" at 11855.46,3473.64 h60
  text "AS SHOWN" at 12042.46,3473.64 h60
  text "X" at 12756.46,3473.64 h60
  text "NC_DRILL FILES" at 12893.46,3473.64 h60
  text "PTH MIN COPPER THICKNESS:" at 11207.23,3315.64 h60
  text "X" at 12557.46,3315.64 h60
  text "1MIL" at 12694.46,3315.64 h60
  text "OTHER" at 13191.46,3315.64 h60
  text "BOARD FINISH:" at 11132.46,3156.64 h60
  text "SILKSCREEN:" at 11287.68,3038.64 h60
  text "X" at 12236.46,3038.64 h60
  text "TOP" at 12362.46,3038.64 h60
  text "X" at 12746.46,3038.64 h60
  text "BOTTOM" at 12873.46,3038.64 h60
  text "SILKSCREEN COLOR:" at 11287.68,2871.64 h60
  text "X" at 12235.42,2871.64 h60
  text "WHITE" at 12362.46,2871.64 h60
  text "OTHER" at 12873.46,2871.64 h60
  text "SOLDER RESIST COLOR:" at 11287.68,2701.64 h60
  text "X" at 11855.42,2542.44 h60
  text "GREEN" at 11982.46,2542.44 h60
  text "BLUE" at 12573.46,2542.44 h60
  text "OTHER" at 13111.46,2542.44 h60
  text "IMMERSION GOLD (ENIG)" at 12193.46,2353.92 h60
  text "SURFACE FINISH:" at 11132.46,2349.64 h60
  text "Pb-FREE HASL" at 13425.75,2349.64 h60
  text "HASL" at 12638.92,2206.64 h60
  text "OTHER" at 12193.46,2192.64 h60
  text "X" at 12002.5,2192.5 h60
  text "ARRAY/PANEL:" at 11132.46,2013.64 h60
  text "CUT AND TRIM PER MECH LAYER 1" at 12193.46,2009.35 h60
  text "N.C. ROUTE" at 12193.46,1857.64 h60
  text "V. SCORE" at 13059.46,1857.64 h60
  text "CERTIFICATION:" at 11132.46,1720.64 h60
  text "MATERIALS AND WORKMANSHIP FOR ALL PCBS" at 11857.46,1720.64 h60
  text "TO MEET OR EXCEED THE REQUIREMENTS OF:" at 11857.46,1622.64 h60
  text "X" at 11483.96,1486.13 h60
  text "ANSI IPC-A-600F CLASS ->" at 11622.96,1486.13 h60
  text "X" at 13262.02,1486.13 h60
  text "2" at 13380.96,1486.14 h60
  text "1" at 13065.96,1484.64 h60
  text "3" at 13734.96,1484.64 h60
  text "X" at 11486.02,1326.64 h60
  text "UL 94V-0" at 11622.96,1326.64 h60
  text "X" at 12298.02,1326.64 h60
  text "RoHS" at 12434.96,1326.64 h60
  text "OTHER" at 13079.36,1326.64 h60
  text "UL FILE NO." at 13476.42,1326.64 h60
  text "ADDITIONAL REQUIREMENTS:" at 11132.46,1185.64 h60
  text "MICROSECTION:" at 11207.23,1070.64 h60
  text "YES" at 12112.96,1070.64 h60
  text "REQUIRED" at 12974.46,914.49 h60
  text "BARE BOARD ELEC. TEST:" at 11207.23,911.64 h60
  text "NONE" at 12512.96,911.64 h60
  text "PER ORDER" at 13566.46,911.64 h60
  text "MANUFACTURER'S ID/LOGO:" at 11207.23,754.64 h60
  text "RAIL" at 12672.96,750.35 h60
  text "METAL" at 13164.77,750.35 h60
  text "SILK" at 13676.46,750.35 h60
  text "X" at 13045,747.5 h60
  text ".Layer_Name" at 377,-1058.49 h60
M11 Gerber Information:
  lines w10: -492,-1130.17 6108,-1130.17 ; -492,-926.83 6110,-926.83 ; -492,-723.5 -492,-1333.5 3513,-1333.5 6110,-1333.5 6110,-723.5 -491.5,-723.5 -491.5,-1333.5 1084,-1333.5 ; 1973,-1333.5 1973,-723.5 ; 3240,-926.83 3240,-723.5 ; 4080,-926.83 4080,-723.5 ; 4702,-1340 4702,-1137.17
  text "ALL ARTWORK VIEWED FROM TOP SIDE" at -428.5,-855.67 h60
  text "BOARD #:" at 2048,-855.67 h60
  text ".PRJ_Number" at 2593.5,-855.67 h60
  text "REV:" at 3438,-855.67 h60
  text ".PCB_Rev" at 3729.5,-855.67 h60
  text "SVN REV:" at 4276,-855.67 h60
  text ".VersionControl_RevNumber" at 4782,-855.67 h60
  text "LAYER NAME =" at -428.5,-1058.49 h60
  text "PLOT NAME =" at -428.5,-1264.34 h60
  text ".plot_File_Name" at 377,-1264.34 h60
  text "GENERATED    :" at 2050,-1264.34 h60
  text ".Print_Date" at 2919.5,-1264.34 h60
  text ".Print_Time" at 3648.5,-1264.34 h60
  text "TEXAS INSTRUMENTS" at 4913,-1264.34 h60
M12 Stackup:
  lines w1: 3085,-200 3337,-200 3337,1571.65 3085,1571.65 3085,-200
  lines w25: 3535,-200 3535,227.5 3587.5,280 3782.5,280 3802.5,300 4180,300 4247.5,367.5 4457.5,367.5
  text ".Layer_Name" at 377,-1058.49 h60
M13 Component Bodies Top:
  text ".Layer_Name" at 377,-1058.49 h60
M14 Component Bodies Bottom:
  text ".Layer_Name" at 377,-1058.49 h60
M15 Courtyards Top:
  text ".Layer_Name" at 377,-1058.49 h60
M16 Courtyards Bottom:
  text ".Layer_Name" at 377,-1058.49 h60
Drill Drawing:
  lines w1: 3320,-175 3320,-432.5 3367.5,-480 3477.5,-480 ; 3107.5,-175 3107.5,20 3525,20 3525,-175 3107.5,-175
  text ".legend" at 5695,193 h60
  text "Drill Table" at 5720,8 h60
  text "PLACE MFGRS LOGO, UL FLAMMABILITY RATING, Tg TEMP, UL FILE NO AND" at 3502.5,-475 h60
  text "DATE CODE HERE IN ETCH BOTTOM SIDE [IF YOU EXCEED THIS AREA, SAFETY SPACING WILL BE VIOLATED]" at 3502.5,-550 h60
  text ".Layer_Name" at 377,-1058.49 h60

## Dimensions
-200,-200 to 5500,-200 on M2 Board Dimensions
-200,-200 to -200,1571.65 on M2 Board Dimensions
